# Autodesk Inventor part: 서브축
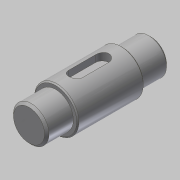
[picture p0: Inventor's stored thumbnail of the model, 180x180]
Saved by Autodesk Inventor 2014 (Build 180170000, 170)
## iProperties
Created: 2019-03
Part Number: 서브축
Material: 강철, 연강
Document SubType Name: Modeling
Designer: mduedu
Density: 1 g/cm^3
Appearance: 강철
Author: mduedu
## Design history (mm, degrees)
sketch "스케치1"
  geometry: L1 (0, 0)-(12, 0); L2 (12, 0)-(12, 8); L3 (12, 8)-(0, 8); L4 (0, 8)-(0, 0); L5 (12, 0)-(42, 0); L6 (42, 0)-(42, 10); L7 (42, 10)-(12, 10); L8 (12, 10)-(12, 0); L9 (42, 0)-(55, 0); L10 (55, 0)-(55, 8); L11 (55, 8)-(42, 8); L12 (42, 8)-(42, 0)
  constraints: 24 end point, 6 parallel, 3 horizontal, 3 perpendicular
  dimensions: "d0" = 16 diameter of L3 L1; "d2" = 20 diameter of L7 L5; "d3" = 16 diameter of L11 L9; "d4" = 12 distance of L2.end L3.end; "d5" = 30 distance of L6.end L7.end; "d6" = 55 distance between parallel lines of L10 L4
revolve "회전1" sketch "스케치1" stored, may be unused: angle "d7" = 90 deg
node "작업 평면1"
sketch "스케치2" dims "d10" = 18
  geometry: L1 (6, -3)-(-6, -3); L2 (-6, -3)-(-6, 3); L3 (-6, 3)-(6, 3); L4 (6, 3)-(6, -3); L5 (15, 10)-(15, -10) reference; 3 further points
  constraints: 8 end point, 2 midpoint, 2 parallel, 2 vertical alignment, 1 horizontal, 1 horizontal alignment, 1 perpendicular, 4 other
  dimensions: "d8" = 6 distance between parallel lines of L3 L1; "d11" = 6 dimension on L5
extrude "돌출1" cut sketch "스케치2" distance "d12" = 3.5; taper "d13" = 0 deg
chamfer "모따기1" distance "d14" = 1; stored, may be unused: second distance "d15" = 2, angle "d16" = 45 deg
chamfer "모따기2" distance "d17" = 0.5; stored, may be unused: second distance "d18" = 2, angle "d19" = 45 deg
node "솔리드1"
